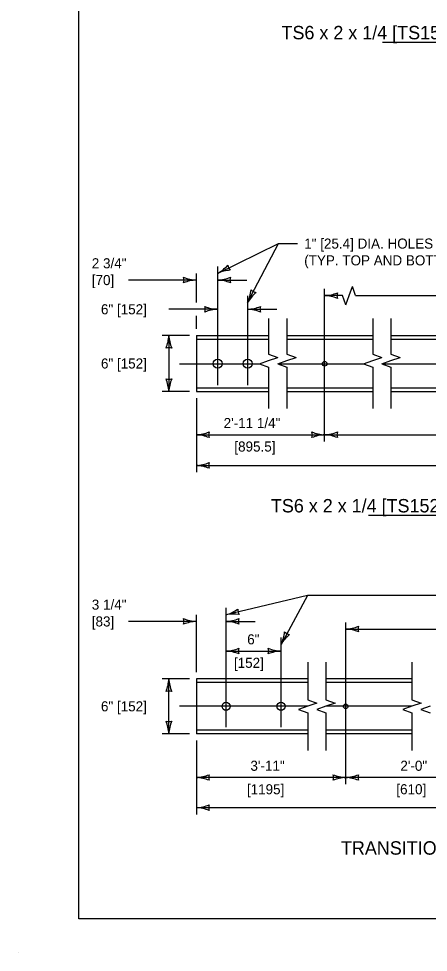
# Model space of a CAD drawing. Extents: x 49991.4 to 50021, y 49987.6 to 50011.4.
# Drawn here: x 49999.02 to 50001.47, y 49987.6 to 49993.16 of the extents above; entities that cross this region are included whole.
import ezdxf

# ---------------------------------------------------------------- set-up
doc = ezdxf.new("R2010")
doc.units = 0
for name, color, linetype in [('Level 1', 7, 'Continuous'), ('Level 2', 7, 'Continuous'), ('Level 3', 7, 'Continuous'), ('Level 4', 7, 'Continuous'), ('Level 5', 7, 'Continuous'), ('Level 6', 7, 'Continuous')]:
    doc.layers.add(name, color=color, linetype=linetype)

msp = doc.modelspace()

# ---------------------------------------------------------------- linework, layer by layer
at = {"layer": 'Level 1'}
for p, q in [((50000.0841, 49991.2758), (50000.0841, 49990.9411)), ((50000.0841, 49991.2758), (50000.5153, 49991.2758)), ((50000.6239, 49991.2758), (50001.1359, 49991.2758)), ((50001.2445, 49991.2758), (50003.3956, 49991.2758)), ((50000.0841, 49990.9411), (50000.5153, 49990.9411)), ((50000.6239, 49990.9411), (50001.1359, 49990.9411)), ((50001.2445, 49990.9411), (50003.3956, 49990.9411)), ((50000.0841, 49989.2289), (50000.0841, 49988.9014)), ((50000.7485, 49989.2289), (50000.0841, 49989.2289)), ((50001.3692, 49989.2289), (50000.8571, 49989.2289)), ((50000.7485, 49988.9014), (50000.0841, 49988.9014)), ((50001.3692, 49988.9014), (50000.8571, 49988.9014)), ((49999.0245, 49987.5988), (49999.0245, 49987.5988))]:
    msp.add_line(p, q, dxfattribs=at)
msp.add_lwpolyline([(49999.3835, 49998.9992), (50016.7501, 49998.9992), (50016.7501, 49987.7988), (49999.3835, 49987.7988)], close=True, dxfattribs=at)
for centre, radius in [((50000.2108, 49991.1072), 0.0274), ((50000.39, 49991.1072), 0.0274), ((50000.8491, 49991.107), 0.0137), ((50000.2615, 49989.0651), 0.0239), ((50000.589, 49989.0651), 0.0239), ((50000.975, 49989.0651), 0.0136)]:
    msp.add_circle(centre, radius, dxfattribs=at)
at = {"layer": 'Level 2'}
for p, q in [((50001.1941, 49993.0245), (50002.7276, 49993.0245)), ((50001.111, 49990.2046), (50002.8772, 49990.2046))]:
    msp.add_line(p, q, dxfattribs=at)
at = {"layer": 'Level 3'}
for p, q in [((50000.2108, 49991.6457), (50000.5742, 49991.8231)), ((50000.39, 49991.4715), (50000.5742, 49991.8231)), ((50000.5742, 49991.8231), (50000.6873, 49991.8231)), ((50000.0841, 49991.6057), (49999.6802, 49991.6057)), ((50000.0841, 49991.4715), (50000.0841, 49991.6457)), ((50000.2108, 49991.6057), (50000.3842, 49991.6057)), ((50000.9951, 49991.5128), (50001.0145, 49991.5676)), ((50001.034, 49991.5128), (50001.0145, 49991.5676)), ((50000.9563, 49991.5128), (50000.8491, 49991.5128)), ((50000.9757, 49991.458), (50000.9563, 49991.5128)), ((50000.9757, 49991.458), (50000.9951, 49991.5128)), ((50001.034, 49991.5128), (50003.8938, 49991.5128)), ((50000.2108, 49991.4315), (49999.9202, 49991.4315)), ((50000.39, 49991.4315), (50000.5634, 49991.4315)), ((50000.0841, 49991.3158), (50000.0841, 49991.3915)), ((50000.0441, 49991.2758), (49999.8802, 49991.2758)), ((49999.9202, 49991.2758), (49999.9202, 49990.9411)), ((50000.0441, 49990.9411), (49999.8802, 49990.9411)), ((50000.0841, 49990.9011), (50000.0841, 49990.4606)), ((50000.0841, 49990.6835), (50000.8491, 49990.6835)), ((50000.8491, 49990.6835), (50002.4573, 49990.6835)), ((50000.0841, 49990.5006), (50004.2084, 49990.5006)), ((50000.7474, 49989.7265), (50000.2615, 49989.611)), ((50000.7474, 49989.7265), (50000.589, 49989.4343)), ((50004.5215, 49989.7265), (50000.7474, 49989.7265)), ((50000.0841, 49989.2689), (50000.0841, 49989.611)), ((50000.0841, 49989.571), (49999.6802, 49989.571)), ((50000.2615, 49989.571), (50000.4349, 49989.571)), ((50000.975, 49989.5254), (50001.7874, 49989.5254)), ((50000.2615, 49989.3943), (50000.589, 49989.3943)), ((50000.0441, 49989.2289), (49999.8802, 49989.2289)), ((49999.9202, 49988.9014), (49999.9202, 49989.2289)), ((50000.0441, 49988.9014), (49999.8802, 49988.9014)), ((49999.9202, 49988.9014), (49999.9202, 49988.9014)), ((50000.0841, 49988.8614), (50000.0842, 49988.4208)), ((50000.975, 49988.6408), (50000.0842, 49988.6408)), ((50001.8186, 49988.6408), (50000.975, 49988.6408)), ((50005.2094, 49988.4608), (50000.0842, 49988.4608))]:
    msp.add_line(p, q, dxfattribs=at)
for centre, radius, start, end in [((50000.0984, 49991.8498), 0.233, 298.8459, 318.0958), ((50000.3, 49991.4421), 0.2223, 93.4746, 113.6581), ((50000.326, 49991.702), 0.0548, 188.1574, 223.8798), ((50000.0933, 49991.8279), 0.2223, 247.456, 267.6395), ((49999.9559, 49991.6057), 0.0548, 342.1388, 17.8612), ((50000.0956, 49991.373), 0.233, 92.8273, 112.0772), ((50000.1993, 49991.8384), 0.233, 272.8273, 292.0772), ((50000.2017, 49991.3836), 0.2223, 67.456, 87.6395), ((50000.339, 49991.6057), 0.0548, 162.1388, 197.8612), ((50000.1785, 49991.5694), 0.233, 335.1708, 354.4206), ((50000.4495, 49991.5851), 0.0548, 224.4823, 260.2046), ((50000.5825, 49991.3603), 0.2223, 129.7995, 149.983), ((50000.8376, 49991.7455), 0.233, 272.8273, 292.0772), ((50000.8399, 49991.2907), 0.2223, 67.456, 87.6395), ((50000.9773, 49991.5128), 0.0548, 162.1388, 197.8612), ((50000.22, 49991.6537), 0.2223, 247.456, 267.6395), ((50000.0826, 49991.4315), 0.0548, 342.1388, 17.8612), ((50000.2223, 49991.1988), 0.233, 92.8273, 112.0772), ((50000.3785, 49991.6642), 0.233, 272.8273, 292.0772), ((50000.3808, 49991.2094), 0.2223, 67.456, 87.6395), ((50000.5182, 49991.4315), 0.0548, 162.1388, 197.8612), ((49999.698, 49991.2849), 0.2223, 337.456, 357.6395), ((50000.1529, 49991.2873), 0.233, 182.8273, 202.0772), ((49999.9202, 49991.1476), 0.0548, 72.1388, 107.8612), ((49999.9202, 49991.0693), 0.0548, 252.1388, 287.8612), ((49999.6874, 49990.9296), 0.233, 2.8273, 22.0772), ((50000.1423, 49990.9319), 0.2223, 157.456, 177.6395), ((50000.0726, 49990.9162), 0.233, 272.8273, 292.0772), ((50000.075, 49990.4613), 0.2223, 67.456, 87.6395), ((50000.2123, 49990.6835), 0.0548, 162.1388, 197.8612), ((50000.8582, 49990.9056), 0.2223, 247.456, 267.6395), ((50000.7209, 49990.6835), 0.0548, 342.1388, 17.8612), ((50000.8606, 49990.4508), 0.233, 92.8273, 112.0772), ((50000.8376, 49990.9162), 0.233, 272.8273, 292.0772), ((50000.8399, 49990.4613), 0.2223, 67.456, 87.6395), ((50000.9773, 49990.6835), 0.0548, 162.1388, 197.8612), ((50000.0726, 49990.7333), 0.233, 272.8273, 292.0772), ((50000.075, 49990.2784), 0.2223, 67.456, 87.6395), ((50000.2123, 49990.5006), 0.0548, 162.1388, 197.8612), ((50000.2013, 49989.825), 0.2223, 285.7227, 305.9062), ((50000.3863, 49989.6407), 0.0548, 175.501, 211.2234), ((50000.3041, 49989.382), 0.233, 81.285, 100.5349), ((50000.0933, 49989.7932), 0.2223, 247.456, 267.6395), ((49999.9559, 49989.571), 0.0548, 342.1388, 17.8612), ((50000.0956, 49989.3383), 0.233, 92.8273, 112.0772), ((50000.25, 49989.8038), 0.233, 272.8273, 292.0772), ((50000.2524, 49989.3489), 0.2223, 67.456, 87.6395), ((50000.3897, 49989.571), 0.0548, 162.1388, 197.8612), ((50000.9636, 49989.7581), 0.233, 272.8278, 292.0777), ((50001.1033, 49989.5254), 0.0548, 162.1393, 197.8617), ((50000.3894, 49989.5321), 0.2223, 333.8945, 354.078), ((50000.7881, 49989.3133), 0.233, 129.4568, 148.7067), ((50000.6501, 49989.547), 0.0548, 223.6728, 259.3952), ((50000.9659, 49989.3032), 0.2223, 67.4565, 87.64), ((50000.2524, 49989.6164), 0.2223, 272.3605, 292.544), ((50000.25, 49989.1616), 0.233, 67.9228, 87.1727), ((50000.3897, 49989.3943), 0.0548, 162.1388, 197.8612), ((50000.5982, 49989.6164), 0.2223, 247.456, 267.6395), ((50000.4608, 49989.3943), 0.0548, 342.1388, 17.8612), ((50000.6005, 49989.1616), 0.233, 92.8273, 112.0772), ((49999.698, 49989.2381), 0.2223, 337.456, 357.6395), ((50000.1529, 49989.2404), 0.233, 182.8273, 202.0772), ((49999.9202, 49989.1007), 0.0548, 72.1388, 107.8612), ((49999.9202, 49989.0296), 0.0548, 252.1388, 287.8612), ((49999.6874, 49988.8899), 0.233, 2.8273, 22.0772), ((50000.1423, 49988.8922), 0.2223, 157.456, 177.6395), ((50000.075, 49988.8629), 0.2223, 272.3605, 292.544), ((50000.2124, 49988.6408), 0.0548, 162.1388, 197.8612), ((50000.8468, 49988.6408), 0.0548, 342.1388, 17.8612), ((50000.9865, 49988.8735), 0.233, 247.9228, 267.1727), ((50000.9659, 49988.8629), 0.2223, 272.3605, 292.544), ((50001.1033, 49988.6408), 0.0548, 162.1388, 197.8612), ((50000.0727, 49988.4081), 0.233, 67.9228, 87.1727), ((50000.9842, 49988.4187), 0.2223, 92.3605, 112.544), ((50000.9636, 49988.4081), 0.233, 67.9228, 87.1727), ((50000.0727, 49988.6935), 0.233, 272.8273, 292.0772), ((50000.2124, 49988.4608), 0.0548, 162.1388, 197.8612), ((50000.0751, 49988.2387), 0.2223, 67.456, 87.6395)]:
    msp.add_arc(centre, radius, start, end, dxfattribs=at)
at = {"layer": 'Level 4'}
for p, q in [((50000.0841, 49991.2542), (50000.5153, 49991.2542)), ((50000.6239, 49991.2542), (50001.1359, 49991.2542)), ((50001.2445, 49991.2542), (50003.3956, 49991.2542)), ((50000.0841, 49990.9626), (50000.5153, 49990.9626)), ((50000.6239, 49990.9626), (50001.1359, 49990.9626)), ((50001.2445, 49990.9626), (50003.3956, 49990.9626)), ((50000.7485, 49989.2074), (50000.0841, 49989.2074)), ((50001.3692, 49989.2074), (50000.8571, 49989.2074)), ((50000.7485, 49988.9229), (50000.0841, 49988.9229)), ((50001.3692, 49988.9229), (50000.8571, 49988.9229))]:
    msp.add_line(p, q, dxfattribs=at)
at = {"layer": 'Level 5'}
for p, q in [((50000.2108, 49991.6857), (50000.2108, 49990.9798)), ((50000.8491, 49990.6435), (50000.8491, 49991.5528)), ((50000.39, 49991.5115), (50000.39, 49990.9798)), ((49999.9841, 49991.107), (50000.463, 49991.107)), ((50000.5716, 49991.107), (50001.0837, 49991.107)), ((50001.1923, 49991.107), (50003.448, 49991.107)), ((50000.2615, 49988.9413), (50000.2615, 49989.6511)), ((50000.975, 49988.6008), (50000.975, 49989.5654)), ((50000.589, 49988.9413), (50000.589, 49989.4743)), ((50000.7485, 49989.0651), (49999.9841, 49989.0651)), ((50001.3692, 49989.0651), (50000.8571, 49989.0651))]:
    msp.add_line(p, q, dxfattribs=at)
at = {"layer": 'Level 6'}
for p, q in [((50000.5153, 49991.3758), (50000.5153, 49991.1643)), ((50000.6239, 49991.3758), (50000.6239, 49991.1643)), ((50001.1359, 49991.3758), (50001.1359, 49991.1643)), ((50001.2445, 49991.3758), (50001.2445, 49991.1643)), ((50000.5153, 49991.1643), (50000.5701, 49991.1449)), ((50000.6239, 49991.1643), (50000.6787, 49991.1449)), ((50001.136, 49991.1643), (50001.1908, 49991.1449)), ((50001.2446, 49991.1643), (50001.2994, 49991.1449)), ((50000.4605, 49991.1061), (50000.5153, 49991.1255)), ((50000.4605, 49991.1061), (50000.5153, 49991.0866)), ((50000.5153, 49991.1255), (50000.5701, 49991.1449)), ((50000.5691, 49991.1061), (50000.6239, 49991.1255)), ((50000.5691, 49991.1061), (50000.6239, 49991.0866)), ((50000.6239, 49991.1255), (50000.6787, 49991.1449)), ((50001.0812, 49991.1061), (50001.136, 49991.1255)), ((50001.0812, 49991.1061), (50001.136, 49991.0866)), ((50001.136, 49991.1255), (50001.1908, 49991.1449)), ((50001.1898, 49991.1061), (50001.2446, 49991.1255)), ((50001.1898, 49991.1061), (50001.2446, 49991.0866)), ((50001.2446, 49991.1255), (50001.2994, 49991.1449)), ((50000.5153, 49991.0866), (50000.5153, 49990.8411)), ((50000.6239, 49991.0866), (50000.6239, 49990.8411)), ((50001.1359, 49991.0866), (50001.1359, 49990.8411)), ((50001.2445, 49991.0866), (50001.2445, 49990.8411)), ((50000.7485, 49989.3289), (50000.7485, 49989.104)), ((50000.8571, 49989.3289), (50000.8571, 49989.1039)), ((50001.3692, 49989.3289), (50001.3692, 49989.104)), ((50000.7485, 49989.104), (50000.8034, 49989.0846)), ((50000.8571, 49989.1039), (50000.9119, 49989.0845)), ((50001.3692, 49989.104), (50001.4241, 49989.0846)), ((50000.7486, 49989.0652), (50000.6938, 49989.0458)), ((50000.6938, 49989.0458), (50000.7485, 49989.0262)), ((50000.8034, 49989.0846), (50000.7486, 49989.0652)), ((50000.8571, 49989.0651), (50000.8023, 49989.0457)), ((50000.8023, 49989.0457), (50000.8571, 49989.0261)), ((50000.9119, 49989.0845), (50000.8571, 49989.0651)), ((50001.3693, 49989.0652), (50001.3145, 49989.0458)), ((50001.3145, 49989.0458), (50001.3692, 49989.0262)), ((50001.4241, 49989.0846), (50001.3693, 49989.0652)), ((50001.4778, 49989.0651), (50001.423, 49989.0457)), ((50001.423, 49989.0457), (50001.4778, 49989.0261)), ((50000.7485, 49989.0262), (50000.7485, 49988.8014)), ((50000.8571, 49989.0261), (50000.8571, 49988.8014)), ((50001.3692, 49989.0262), (50001.3692, 49988.8014))]:
    msp.add_line(p, q, dxfattribs=at)

# ---------------------------------------------------------------- texts
at = {"layer": 'Level 2'}
for s, height, p in [('TS6 x 2 x 1/4 [TS152 x 51 x 6.4] BR. APP. SECT. LOWER RAIL NO.1', 0.08, (50000.5919, 49993.0405)), ('1" [25.4] DIA. HOLES (2) PLCS.', 0.06, (50000.7273, 49991.7931)), ('2 3/4"', 0.06, (49999.4606, 49991.6757)), ('(TYP. TOP AND BOTTOM)', 0.06, (50000.7273, 49991.6931)), ('[70]', 0.06, (49999.4606, 49991.5757)), ('6" [152]', 0.06, (49999.5152, 49991.4015)), ('6" [152]', 0.06, (49999.5152, 49991.0784)), ('2\'-11 1/4"', 0.06, (50000.2468, 49990.7235)), ('[895.5]', 0.06, (50000.3107, 49990.5835)), ('TS6 x 2 x 1/4 [TS152 x 51 x 6.4]  BR. APP. SECT. LOWER RAIL NO. 2', 0.08, (50000.5287, 49990.2206)), ('3 1/4"', 0.06, (49999.4606, 49989.641)), ('[83]', 0.06, (49999.4606, 49989.541)), ('6"', 0.06, (50000.3873, 49989.4343)), ('[152]', 0.06, (50000.3081, 49989.2943)), ('6" [152]', 0.06, (49999.5152, 49989.0351)), ('3\'-11"', 0.06, (50000.4066, 49988.6808)), ('2\'-0"', 0.06, (50001.3007, 49988.6808)), ('[1195]', 0.06, (50000.3855, 49988.5408)), ('[610]', 0.06, (50001.2767, 49988.5408)), ('TRANSITION RAIL (TS6 x 6 x 3/16 [TS152 x 152 x 4.8])', 0.08, (50000.9464, 49988.1808))]:
    msp.add_text(s, height=height, dxfattribs=at).set_placement(p)

doc.saveas('drawing.dxf')
